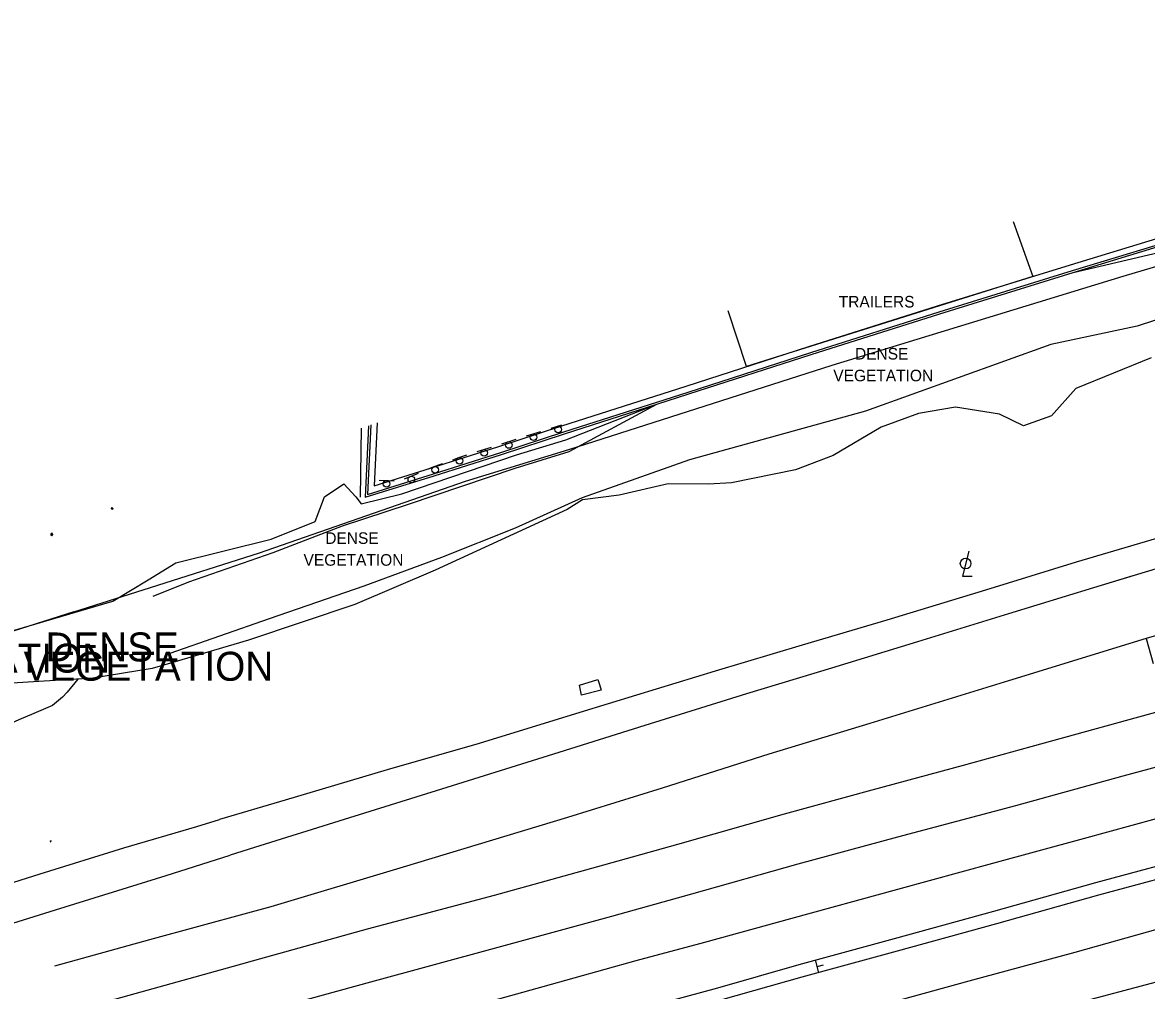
# Model space of a CAD drawing. Extents: x 2129547 to 2134906, y 657330 to 659734.
# Drawn here: x 2130826.3 to 2131098, y 658118.5 to 658352.4 of the extents above; entities that cross this region are included whole.
import ezdxf

# ---------------------------------------------------------------- set-up
doc = ezdxf.new("R2010")
doc.units = 0
for name, color, linetype in [('DR_X_Paved_Gutter', 7, 'Continuous'), ('LT_X_Poles', 7, 'Continuous'), ('PM_X_Edge_Line', 7, 'Continuous'), ('PM_X_Lane_Line', 7, 'Continuous'), ('PV_X_Curb', 7, 'Continuous'), ('PV_X_EOP2', 7, 'Continuous'), ('PV_X_Parking_Lot', 7, 'Continuous'), ('PV_X_Shoulder', 7, 'Continuous'), ('RD_X_Concrete_Barrier', 7, 'Continuous'), ('RD_X_Concrete_Pad', 7, 'Continuous'), ('RD_X_Fence', 7, 'Continuous'), ('RD_X_GR_Rt', 7, 'Continuous'), ('RD_X_Misc_Items', 7, 'Continuous'), ('SN_X_Public', 7, 'Continuous'), ('VG_X_Cells', 7, 'Continuous'), ('VG_X_Shrub_Line_Lt', 7, 'Continuous'), ('VG_X_Text', 7, 'Continuous'), ('VG_X_Tree_Line_Lt', 7, 'Continuous')]:
    doc.layers.add(name, color=color, linetype=linetype)

# ---------------------------------------------------------------- blocks, each defined once
blk = doc.blocks.new('LPOLE')
at = {"layer": 'LT_X_Poles'}
blk.add_lwpolyline([(0.01, 0.0375), (-0.01, -0.0385), (0.02, -0.0385)], dxfattribs=at)
blk.add_circle((0, 0), 0.0165, dxfattribs=at)
blk = doc.blocks.new('SGN1P')
at = {"layer": 'SN_X_Public'}
for p, q in [((0, 0), (-0.02032, 0)), ((0, 0.02032), (0, -0.02032))]:
    blk.add_line(p, q, dxfattribs=at)

msp = doc.modelspace()

# ---------------------------------------------------------------- linework, layer by layer
at = {"layer": 'DR_X_Paved_Gutter'}
msp.add_lwpolyline([(2130912.03, 658255.65), (2130911.29, 658240.43), (2130925.18, 658244.78), (2130941.47, 658249.95), (2130956.68, 658254.95), (2130986.72, 658264.55), (2131016.36, 658274.11), (2131047.46, 658283.94), (2131079.63, 658293.88), (2131109.98, 658303.13), (2131149.88, 658315.14), (2131184.74, 658325.53), (2131210.86, 658333.04), (2131210.75, 658347.63)], dxfattribs=at)
at = {"layer": 'LT_X_Poles'}
msp.add_lwpolyline([(2130833.16, 658154.74), (2130833.08, 658154.44), (2130833.2, 658154.44)], dxfattribs=at)
msp.add_circle((2130833.12, 658154.59), 0.065, dxfattribs=at)
at = {"layer": 'PM_X_Edge_Line'}
for points in [[(2130891, 658102.57), (2130905.36, 658106.57), (2130928.7, 658112.95), (2130952.19, 658119.5), (2130974.68, 658125.71), (2130991.22, 658130.21), (2131011.99, 658135.88), (2131037.88, 658143.01), (2131060.83, 658149.3), (2131082.78, 658155.22), (2131106.25, 658161.71), (2131128.24, 658167.69), (2131156.14, 658175.52), (2131181.21, 658182.49), (2131205.87, 658189.24), (2131228.59, 658195.53), (2131252.79, 658202.27), (2131273.67, 658208.13), (2131298.68, 658214.86), (2131324.12, 658221.75), (2131348.82, 658228.57), (2131375.1, 658235.74), (2131400.81, 658242.88)], [(2131105.61, 658222), (2131085.18, 658215.77), (2131064.63, 658209.53), (2131042.64, 658202.78), (2131021.82, 658196.38), (2131001.34, 658190.16), (2130976.76, 658182.51), (2130955.93, 658176.02), (2130927.57, 658167.12), (2130904.11, 658159.8), (2130882.42, 658153.06), (2130876.51, 658151.19)], [(2131391.93, 658213.4), (2131368, 658206.91), (2131341.78, 658199.75), (2131315.24, 658192.47), (2131285.72, 658184.3), (2131257.55, 658176.45), (2131231.68, 658169.56), (2131212.62, 658164.32), (2131190.64, 658158.19), (2131169.84, 658152.49), (2131145.7, 658145.83), (2131125.75, 658140.27), (2131100.74, 658133.28), (2131080.69, 658127.69), (2131055.04, 658120.76), (2131018.49, 658110.67), (2130998.15, 658105.13), (2130976.5, 658099.09), (2130942.37, 658089.65), (2130912.01, 658081.31), (2130898.43, 658077.6)], [(2131124.53, 658211.22), (2131097.92, 658203.59), (2131099.59, 658197.49)], [(2130507.73, 658038.43), (2130546.43, 658050.14), (2130594.19, 658064.34), (2130631.31, 658075.34), (2130677.05, 658089.14), (2130720.52, 658102.5), (2130758.97, 658114.48), (2130792.54, 658124.9), (2130834.3, 658137.98), (2130861.02, 658146.3), (2130876.51, 658151.19)]]:
    msp.add_lwpolyline(points, dxfattribs=at)
at = {"layer": 'PM_X_Lane_Line'}
for points in [[(2130883.95, 658126.23), (2130909.74, 658133.43), (2130940.43, 658141.55), (2130966.85, 658148.84), (2130984.68, 658153.87), (2131010.49, 658161.21), (2131031.7, 658166.99), (2131053.74, 658172.98), (2131070.1, 658177.45), (2131103.99, 658186.81), (2131144.51, 658198.18), (2131177.77, 658207.11), (2131211.57, 658216.59), (2131235.4, 658223.12), (2131255.58, 658228.68), (2131276.03, 658234.43), (2131298.07, 658240.54), (2131321.32, 658247), (2131343.87, 658253.31), (2131381.41, 658263.57), (2131428.52, 658276.66)], [(2131394.23, 658253.22), (2131371.64, 658247.1), (2131347.48, 658240.52), (2131325.08, 658234.28), (2131302.56, 658228.11), (2131279.27, 658221.78), (2131255.34, 658215.2), (2131230.51, 658208.32), (2131202.78, 658200.44), (2131175.2, 658193.07), (2131142.99, 658184.04), (2131119.15, 658177.56), (2131092.27, 658170.26), (2131066.31, 658163.11), (2131037.76, 658155.51), (2131013.74, 658149.02), (2130988.03, 658141.76), (2130968.64, 658136.39), (2130940.36, 658128.62), (2130910.43, 658120.51), (2130887.53, 658114.21)], [(2131097.92, 658203.59), (2131064.66, 658193.36), (2131031.14, 658183.03), (2131006.71, 658175.6), (2130980.94, 658167.39), (2130958.05, 658160.33), (2130918.3, 658148.28), (2130886.36, 658138.75), (2130880.68, 658137.19)], [(2131398.2, 658202.88), (2131377.59, 658197.24), (2131355.03, 658191.01), (2131329.48, 658184), (2131308.98, 658178.3), (2131287.17, 658172.05), (2131268.54, 658166.95), (2131249.14, 658161.71), (2131232.12, 658156.84), (2131210.13, 658150.71), (2131191.34, 658145.6), (2131170.47, 658139.83), (2131150.51, 658134.32), (2131128.13, 658128.26), (2131104.27, 658121.56), (2131076.93, 658114.27), (2131045.67, 658105.64), (2131023.04, 658099.46), (2131001.31, 658093.68), (2130986.21, 658089.5), (2130954.6, 658080.73), (2130930.95, 658074.11), (2130910.13, 658068.18), (2130901.91, 658065.91)], [(2130880.68, 658137.19), (2130857.06, 658130.7), (2130834.09, 658124.36)], [(2130517.26, 658025.11), (2130555.6, 658035.62), (2130596.09, 658046.96), (2130635.43, 658057.75), (2130673, 658068.21), (2130712.86, 658079.14), (2130754.47, 658090.52), (2130796.26, 658102.11), (2130842.82, 658114.83), (2130877.34, 658124.38), (2130883.95, 658126.23)]]:
    msp.add_lwpolyline(points, dxfattribs=at)
at = {"layer": 'PV_X_Curb'}
msp.add_lwpolyline([(2130909.99, 658254.98), (2130909.16, 658237.67), (2130925.79, 658242.87), (2130942.09, 658248.05), (2130957.3, 658253.05), (2130979.6, 658260.17), (2130987.33, 658262.65), (2131016.97, 658272.21), (2131048.06, 658282.04), (2131080.22, 658291.97), (2131110.56, 658301.22), (2131150.45, 658313.22), (2131162.19, 658316.72), (2131185.31, 658323.61), (2131212.87, 658331.54), (2131212.75, 658347.8), (2131212.76, 658348.23)], dxfattribs=at)
at = {"layer": 'PV_X_EOP2'}
for points in [[(2130891, 658102.57), (2130905.36, 658106.57), (2130928.7, 658112.95), (2130952.19, 658119.5), (2130974.68, 658125.71), (2130991.22, 658130.21), (2131011.99, 658135.88), (2131037.88, 658143.01), (2131060.83, 658149.3), (2131082.78, 658155.22), (2131106.25, 658161.71), (2131128.24, 658167.69), (2131156.14, 658175.52), (2131181.21, 658182.49), (2131205.87, 658189.24), (2131228.59, 658195.53), (2131252.79, 658202.27), (2131273.67, 658208.13), (2131298.68, 658214.86), (2131324.12, 658221.75), (2131348.82, 658228.57), (2131375.1, 658235.74), (2131400.81, 658242.88)], [(2131094.65, 658218.66), (2131085.18, 658215.77), (2131064.63, 658209.53), (2131042.64, 658202.78), (2131021.82, 658196.38), (2131001.34, 658190.16), (2130976.76, 658182.51), (2130955.93, 658176.02), (2130927.57, 658167.12), (2130904.11, 658159.8), (2130882.42, 658153.06), (2130876.51, 658151.19)], [(2131391.93, 658213.4), (2131368, 658206.91), (2131341.78, 658199.75), (2131315.24, 658192.47), (2131285.72, 658184.3), (2131257.55, 658176.45), (2131231.68, 658169.56), (2131212.62, 658164.32), (2131190.64, 658158.19), (2131169.84, 658152.49), (2131145.7, 658145.83), (2131125.75, 658140.27), (2131100.74, 658133.28), (2131080.69, 658127.69), (2131055.04, 658120.76), (2131018.49, 658110.67), (2130998.15, 658105.13), (2130976.5, 658099.09), (2130942.37, 658089.65), (2130912.01, 658081.31), (2130898.43, 658077.6)], [(2130507.73, 658038.43), (2130546.43, 658050.14), (2130594.19, 658064.34), (2130631.31, 658075.34), (2130677.05, 658089.14), (2130720.52, 658102.5), (2130758.97, 658114.48), (2130792.54, 658124.9), (2130834.3, 658137.98), (2130861.02, 658146.3), (2130876.51, 658151.19)]]:
    msp.add_lwpolyline(points, dxfattribs=at)
at = {"layer": 'PV_X_Parking_Lot'}
msp.add_lwpolyline([(2130910.5, 658255.15), (2130909.69, 658238.36), (2130925.63, 658243.35), (2130941.93, 658248.53), (2130957.14, 658253.52), (2130987.18, 658263.12), (2131016.82, 658272.69), (2131047.9, 658282.51), (2131080.06, 658292.44), (2131110.42, 658301.69), (2131150.31, 658313.7), (2131185.17, 658324.09), (2131212.36, 658331.91), (2131212.25, 658347.81), (2131212.25, 658348.08)], dxfattribs=at)
at = {"layer": 'PV_X_Shoulder'}
for points in [[(2131118.09, 658233.1), (2131098.99, 658227.31), (2131081.01, 658222.02), (2131059.09, 658215.24), (2131035.24, 658208.02), (2131014.76, 658201.93), (2130993.74, 658195.63), (2130974.74, 658189.85), (2130961.01, 658185.65), (2130936.73, 658178.19), (2130914.43, 658171.83), (2130889.82, 658164.49), (2130873.95, 658159.78)], [(2130494.01, 658044.69), (2130534.58, 658056.98), (2130576.5, 658069.39), (2130623.09, 658083.36), (2130668.35, 658097.03), (2130711.95, 658110.36), (2130758.22, 658124.46), (2130800.02, 658136.99), (2130830.63, 658146.71), (2130850.86, 658153), (2130868.47, 658158.15), (2130873.95, 658159.78)]]:
    msp.add_lwpolyline(points, dxfattribs=at)
at = {"layer": 'RD_X_Concrete_Barrier'}
for points in [[(2131391.74, 658229.13), (2131379.32, 658225.19), (2131359.92, 658219.83), (2131338.36, 658213.96), (2131312.24, 658206.8), (2131285.52, 658199.37), (2131257.25, 658191.69), (2131234.72, 658185.34), (2131209.47, 658178.52), (2131183.51, 658171.23), (2131159.15, 658164.59), (2131135.07, 658158.08), (2131111.97, 658151.63), (2131085.68, 658144.48), (2131061.03, 658137.57), (2131037, 658130.96), (2131013.95, 658124.67), (2130994.29, 658119.1), (2130982.69, 658115.91), (2130954.42, 658108.17), (2130930.56, 658101.55), (2130905.86, 658094.77), (2130894.27, 658091.58)], [(2130895.13, 658088.7), (2130906.66, 658091.87), (2130931.36, 658098.66), (2130955.21, 658105.28), (2130983.48, 658113.02), (2130995.09, 658116.21), (2131014.76, 658121.78), (2131037.79, 658128.06), (2131061.83, 658134.68), (2131086.48, 658141.59), (2131112.76, 658148.74), (2131135.87, 658155.19), (2131159.93, 658161.69), (2131184.31, 658168.34), (2131210.27, 658175.63), (2131235.52, 658182.45), (2131258.05, 658188.8), (2131286.32, 658196.47), (2131313.04, 658203.91), (2131339.15, 658211.07), (2131360.71, 658216.94), (2131380.03, 658222.28), (2131393.19, 658225.09)]]:
    msp.add_lwpolyline(points, dxfattribs=at)
at = {"layer": 'RD_X_Concrete_Pad'}
msp.add_lwpolyline([(2130960.93, 658192.28), (2130965.34, 658193.63), (2130965.74, 658192.45), (2130966.21, 658191.09), (2130961.39, 658189.85), (2130961.17, 658191.05)], close=True, dxfattribs=at)
at = {"layer": 'RD_X_Fence'}
for p, q in [((2130908.16, 658254.38), (2130907.91, 658237.74)), ((2130838.77, 658210.01), (2130857.25, 658215.88)), ((2130838.77, 658210.01), (2130818.36, 658203.49))]:
    msp.add_line(p, q, dxfattribs=at)
for points in [[(2130958.33, 658249.24), (2131021.99, 658269.61), (2131092.36, 658291.14), (2131130.38, 658302.4), (2131226.74, 658331.31), (2131226.8, 658352.41)], [(2130857.25, 658215.88), (2130883.64, 658224.26), (2130933.42, 658241.54), (2130958.33, 658249.24)]]:
    msp.add_lwpolyline(points, dxfattribs=at)
at = {"layer": 'RD_X_GR_Rt'}
for p, q in [((2130948.14, 658252.51), (2130951.58, 658253.59)), ((2130954.1, 658254.38), (2130956.68, 658255.19)), ((2130936.23, 658248.72), (2130939.66, 658249.82)), ((2130918.68, 658242.15), (2130922, 658243.53))]:
    msp.add_line(p, q, dxfattribs=at)
for points in [[(2130942.18, 658250.62), (2130944.89, 658251.49), (2130945.61, 658251.71)], [(2130930.3, 658246.75), (2130931.81, 658247.31), (2130933.7, 658247.92)], [(2130924.45, 658244.55), (2130925.18, 658244.85), (2130927.81, 658245.83)], [(2130912.55, 658241.82), (2130914.76, 658241.71), (2130916.15, 658241.63)]]:
    msp.add_lwpolyline(points, dxfattribs=at)
for centre in [(2130949.82, 658252.2), (2130955.78, 658254.07), (2130943.86, 658250.32), (2130937.9, 658248.42), (2130926.09, 658244.34), (2130931.95, 658246.51), (2130920.31, 658241.96), (2130914.31, 658240.93)]:
    msp.add_circle(centre, 0.8, dxfattribs=at)
at = {"layer": 'RD_X_Misc_Items'}
for points in [[(2130857.88, 658213.75), (2130866.51, 658217.26), (2130886.93, 658224.32), (2130903.66, 658230.77), (2130919.66, 658236.04), (2130945.37, 658244.73), (2130958.47, 658248.73), (2130979.6, 658260.17), (2130987.33, 658262.65), (2131016.97, 658272.21), (2131048.06, 658282.04), (2131080.22, 658291.97), (2131111.51, 658299.3), (2131145.88, 658310.07), (2131162.19, 658316.72), (2131185.31, 658323.61), (2131212.87, 658331.54)], [(2131065.73, 658304.34), (2131070.5, 658291.06), (2131001.33, 658269.26), (2130996.85, 658282.7)], [(2131125.02, 658288.63), (2131095.68, 658279.05), (2131074.87, 658274.59), (2131030.05, 658258.49), (2130987.54, 658246.73), (2130961.56, 658237.55), (2130945.4, 658230.18), (2130927.61, 658223.15), (2130908.82, 658216.18), (2130885.98, 658208.34), (2130861.98, 658199.97)]]:
    msp.add_lwpolyline(points, dxfattribs=at)
at = {"layer": 'VG_X_Cells'}
for p, q in [((2130847.74, 658234.99), (2130847.99, 658234.99)), ((2130847.99, 658234.99), (2130847.77, 658235.05)), ((2130847.99, 658234.99), (2130847.78, 658234.91)), ((2130847.99, 658234.99), (2130847.79, 658234.88)), ((2130847.99, 658234.99), (2130847.8, 658235.11)), ((2130847.99, 658234.99), (2130847.8, 658234.84)), ((2130847.99, 658234.99), (2130847.82, 658235.17)), ((2130847.99, 658234.99), (2130847.84, 658234.82)), ((2130847.99, 658234.99), (2130847.88, 658234.79)), ((2130847.99, 658234.99), (2130847.91, 658234.78)), ((2130847.99, 658234.99), (2130847.93, 658235.22)), ((2130847.99, 658234.99), (2130847.93, 658234.75)), ((2130847.99, 658234.99), (2130847.96, 658234.76)), ((2130847.99, 658234.99), (2130848.05, 658235.23)), ((2130847.99, 658234.99), (2130848.12, 658235.19)), ((2130847.99, 658234.99), (2130848.17, 658235.13)), ((2130847.99, 658234.99), (2130848.23, 658235.07)), ((2130847.99, 658234.99), (2130848.22, 658235)), ((2130847.99, 658234.73), (2130847.99, 658234.99)), ((2130847.99, 658234.99), (2130848.04, 658234.76)), ((2130847.99, 658234.99), (2130848.09, 658234.76)), ((2130847.99, 658234.99), (2130848.12, 658234.8)), ((2130847.99, 658234.99), (2130848.17, 658234.82)), ((2130847.99, 658234.99), (2130848.18, 658234.86)), ((2130847.99, 658234.99), (2130848.21, 658234.9)), ((2130847.99, 658234.99), (2130848.23, 658234.94))]:
    msp.add_line(p, q, dxfattribs=at)
msp.add_circle((2130833.4, 658228.71), 0.012, dxfattribs=at)
for centre, radius, start, end in [((2130833.23, 658228.81), 0.0735, 39.0625, 279.5412), ((2130833.26, 658228.63), 0.0987, 96.1722, 320.5737), ((2130833.35, 658228.88), 0.0658, 354.0047, 205.9741), ((2130833.45, 658228.58), 0.114, 184.9476, 19.4572), ((2130833.49, 658228.85), 0.0776, 323.83, 165.0376), ((2130833.57, 658228.71), 0.0957, 259.1453, 101.4596)]:
    msp.add_arc(centre, radius, start, end, dxfattribs=at)
at = {"layer": 'VG_X_Shrub_Line_Lt'}
msp.add_lwpolyline([(2130839.74, 658193.73), (2130837.13, 658190.62), (2130836, 658189.34), (2130833.61, 658187.34), (2130829.06, 658185.47), (2130825.43, 658183.94), (2130823.54, 658183.02), (2130821.8, 658181.74), (2130820.27, 658179.97), (2130818.27, 658176.29), (2130816.51, 658173.69), (2130815.34, 658172.48), (2130813.33, 658170.8), (2130805.95, 658167.89)], dxfattribs=at)
at = {"layer": 'VG_X_Tree_Line_Lt'}
for points in [[(2130856.69, 658217.74), (2130863.37, 658221.82), (2130886.46, 658227.54), (2130897.05, 658231.84), (2130899.32, 658237.75), (2130903.96, 658240.89), (2130906.89, 658237.77), (2130908.2, 658236.13), (2130918.01, 658238.49), (2130945.72, 658247.92), (2130957.68, 658251.59), (2130979.6, 658260.17), (2130987.33, 658262.65), (2131016.97, 658272.21), (2131048.06, 658282.04), (2131080.22, 658291.97), (2131111.51, 658299.3)], [(2131099.07, 658271.37), (2131080.92, 658263.98), (2131075.02, 658257.36), (2131068.27, 658254.94), (2131062.48, 658257.73), (2131051.81, 658259.49), (2131042.84, 658257.89), (2131033.83, 658254.6), (2131022.28, 658247.79), (2131013.15, 658244.34), (2130997.67, 658241.15), (2130992.14, 658240.86), (2130982.36, 658240.92), (2130970.56, 658238.19), (2130961.69, 658237.06), (2130957.99, 658234.7), (2130926.09, 658220.1), (2130906.65, 658211.81), (2130880.94, 658203.13), (2130862.64, 658197.78)], [(2130862.64, 658197.78), (2130857.69, 658196.33), (2130843.37, 658193.96), (2130821.2, 658192.57), (2130815.57, 658194.27), (2130819.56, 658201.51), (2130820.22, 658204.37), (2130848.17, 658212.54), (2130856.69, 658217.74)]]:
    msp.add_lwpolyline(points, dxfattribs=at)

# ---------------------------------------------------------------- block references
at = {"layer": 'LT_X_Poles', "xscale": 78.74000000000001, "yscale": 78.74000000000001}
msp.add_blockref('LPOLE', (2131054.26, 658221.67), dxfattribs=at)
at = {"layer": 'SN_X_Public', "xscale": 78.74, "yscale": 78.74, "rotation": -165.66955055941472}
msp.add_blockref('SGN1P', (2131018.39, 658124.32), dxfattribs=at)

# ---------------------------------------------------------------- texts
at = {"layer": 'RD_X_Misc_Items'}
msp.add_text('TRAILERS', height=2.8, dxfattribs=at).set_placement((2131023.6, 658283.54))
at = {"layer": 'VG_X_Text'}
for s, height, p in [('DENSE', 2.8, (2131027.53, 658270.97)), ('VEGETATION', 2.8, (2131022.28, 658265.7)), ('DENSE', 2.8, (2130899.51, 658226.41)), ('VEGETATION', 2.8, (2130894.26, 658221.14)), ('DENSE', 7, (2130831.87, 658198.01)), ('VEGETATION', 7, (2130787.19, 658195.31)), ('VEGETATION', 7, (2130826.61, 658193.35))]:
    msp.add_text(s, height=height, dxfattribs=at).set_placement(p)

doc.saveas('drawing.dxf')
